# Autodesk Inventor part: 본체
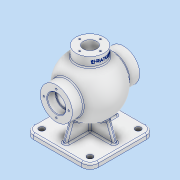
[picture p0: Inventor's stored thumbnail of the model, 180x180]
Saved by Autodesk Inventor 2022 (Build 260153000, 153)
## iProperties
Created: 2024-04
Part Number: 본체
Material: 알루미늄 6061
Document SubType Name: Modeling
Designer: Admin
Mass: 1526.9 g
Surface Area: 1171.86 cm^2
Volume: 565.52 cm^3
Density: 2.7 g/cm^3
Appearance: 알루미늄 - 평지
Author: Admin
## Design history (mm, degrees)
sketch "스케치1"
  geometry: C1 r 54 at (0, 0); 1 further point
  constraints: 1 centre point, 1 coincident
  dimensions: "d0" = 108 diameter of C1
extrude "돌출1" new body sketch "스케치1" stored distance "d1" = 108; taper "d2" = 0 deg
fillet "모깎기1" dims "d3" = 54
node "작업 평면2"
sketch "스케치2"
  geometry: L1 (-46.5, -62.5)-(46.5, -62.5); L2 (62.5, -46.5)-(62.5, 46.5); L3 (46.5, 62.5)-(-46.5, 62.5); L4 (-62.5, 46.5)-(-62.5, -46.5); L5 (-62.5, -62.5)-(62.5, 62.5); L6 (62.5, -62.5)-(-62.5, 62.5); A1 r 16 centre (46.5, 46.5) between (62.5, 46.5) and (46.5, 62.5); A2 r 16 centre (46.5, -46.5) between (46.5, -62.5) and (62.5, -46.5); A3 r 16 centre (-46.5, -46.5) between (-62.5, -46.5) and (-46.5, -62.5); A4 r 16 centre (-46.5, 46.5) between (-46.5, 62.5) and (-62.5, 46.5); 1 further point
  constraints: 12 end point, 8 point on circle, 8 point on line, 8 tangent, 4 centre point, 3 equal radius, 2 midpoint, 2 parallel, 1 horizontal, 1 perpendicular
  dimensions: "d6" = 125 distance of L6.start L5.end; "d7" = 125 distance of L5.start L6.start (= d6); "d8" = 16 radius of A1
extrude "돌출2" join sketch "스케치2" distance "d9" = 10; taper "d10" = 0 deg
sketch "스케치3"
  geometry: L1 (-112.8, 0)-(81.8, 0) reference; L2 (0, -87.5)-(0, 87.5) reference; L3 (-85, 87.5)-(-85, -87.5) reference; L4 (-85, 46.5)-(-85, 62.5) reference; L5 (0, 23.202)-(0, -23.202); L6 (-85, -62.5)-(-85, -46.5) reference; L7 (-85, 62.5)-(-75, 62.5) reference; L8 (-75, 46.5)-(-75, 62.5) reference; L9 (-75, -62.5)-(-75, -46.5) reference; L10 (-85, -46.5)-(-85, 46.5) reference; L11 (0, 23.202)-(-75, 50.5); L12 (-75, 50.5)-(-75, -50.5); L13 (-75, -50.5)-(0, -23.202); L14 (-75, -46.5)-(-75, 46.5) reference; 5 further points
  constraints: 8 end point, 3 midpoint, 2 symmetric about line, 1 parallel, 1 point on line, 1 vertical
  dimensions: "d13" = 20 deg angle of L7 L11; "d14" = 12 distance from line of L7 L11.end
extrude "돌출3" join sketch "스케치3" stored distance "d15" = 8; taper "d16" = 0 deg
sketch "스케치4"
  geometry: L1 (46.5, -75)-(-46.5, -75) reference; L2 (0, -112.8)-(0, 81.8) reference; L3 (-87.5, 0)-(87.5, 0) reference; L4 (-23.202, 0)-(23.202, 0); L5 (23.202, 0)-(50.5, -75); L6 (50.5, -75)-(-50.5, -75); L7 (-50.5, -75)-(-23.202, 0); L8 (-62.5, -85)-(-62.5, -75) reference; 3 further points
  constraints: 8 end point, 4 midpoint, 2 symmetric about line, 1 horizontal
  dimensions: "d17" = 20 deg angle of L8 L7; "d18" = 12 distance from line of L8 L6.end
extrude "돌출4" join sketch "스케치4" stored distance "d19" = 8; taper "d20" = 0 deg
node "작업 평면3"
sketch "스케치5"
  geometry: C1 r 31 at (0, 0); 1 further point
  constraints: 1 centre point, 1 coincident
  dimensions: "d22" = 62 diameter of C1
extrude "돌출5" join sketch "스케치5" distance "d23" = 130; taper "d24" = 0 deg
node "작업 평면4"
sketch "스케치6"
  geometry: C1 r 27 at (0, 0); 1 further point
  constraints: 1 centre point, 1 coincident
  dimensions: "d26" = 54 diameter of C1
extrude "돌출6" join sketch "스케치6" stored distance "d27" = 130; taper "d28" = 0 deg
sketch "스케치9"
  geometry: C1 r 15 at (0, 0); 1 further point
  constraints: 1 centre point, 1 coincident
  dimensions: "d29" = 30 diameter of C1
extrude "돌출7" cut sketch "스케치9" stored distance "d31" = 10; taper "d32" = 0 deg
sketch "스케치11"
  geometry: C1 r 13 at (0, 0); 1 further point
  constraints: 1 centre point, 1 coincident
  dimensions: "d33" = 26 diameter of C1
extrude "돌출8" cut sketch "스케치11" stored distance "d34" = 10; taper "d35" = 0 deg
sketch "스케치12"
  geometry: L1 (0, -91)-(0, 91) reference; L2 (0, -128.405)-(0, 139.748); A1 r 44 centre (0, 0) between (0, -44) and (0, 44); 3 further points
  constraints: 5 point on line, 2 end point, 2 point on circle, 1 centre point, 1 coincident
  dimensions: "d36" = 44 radius of A1
revolve "회전1" sketch "스케치12" stored, may be unused: angle "d37" = 90 deg
sketch "스케치13"
  geometry: C1 r 17.5 at (0, 0); 1 further point
  constraints: 1 centre point, 1 coincident
  dimensions: "d38" = 35 diameter of C1
extrude "돌출9" cut sketch "스케치13" distance "d39" = 16; taper "d40" = 0 deg
sketch "스케치14"
  geometry: L1 (87.5, 0)-(-87.5, 0) reference; L2 (0, -115)-(0, 95) reference; 2 further points
  constraints: 1 point on line
  dimensions: "d41" = 24 distance from line of L1 point (0, 24)
hole "구멍1" sketch "스케치14" at (0, 24) diameter "d42" = 3.242; stored, may be unused: countersink angle "d46" = 90 deg, drill point angle "d48" = 118 deg; dims "d43" = 12, "d44" = 4, "d45" = 2, "d47" = 15
sketch "스케치15"
  geometry: L1 (0, 91)-(0, -91) reference; 2 further points
  constraints: 1 point on line
  dimensions: "d52" = 20 distance of point (0, 0) point (0, -20)
hole "구멍2" sketch "스케치15" at (0, -20) diameter "d53" = 3.242; stored, may be unused: countersink angle "d57" = 90 deg, drill point angle "d59" = 118 deg; dims "d54" = 9, "d55" = 4, "d56" = 2, "d58" = 11
fillet "모깎기2" dims "d63" = 3
fillet "모깎기3" dims "d64" = 3
sketch "스케치16"
  geometry: A1 r 16 centre (-46.5, -46.5) between (-62.5, -46.5) and (-46.5, -62.5) reference; A2 r 16 centre (-46.5, 46.5) between (-46.5, 62.5) and (-62.5, 46.5) reference; A3 r 16 centre (46.5, 46.5) between (62.5, 46.5) and (46.5, 62.5) reference; A4 r 16 centre (46.5, -46.5) between (46.5, -62.5) and (62.5, -46.5) reference; 5 further points
  constraints: 4 coincident
hole "구멍3" sketch "스케치16" at (-46.5, -46.5), (-46.5, 46.5), (46.5, 46.5), (46.5, -46.5) diameter "d68" = 11; stored, may be unused: countersink angle "d72" = 90 deg, drill point angle "d74" = 118 deg; dims "d69" = 9, "d70" = 4, "d71" = 2, "d73" = 11
fillet "모깎기4" dims "d75" = 3
node "작업 평면5"
sketch "스케치17"
  geometry: L1 (-115, 0)-(95, 0) reference; L2 (65, -27)-(65, 27) reference; 2 further points
  constraints: 1 point on line, 1 other
  dimensions: "d77" = 9 distance from line of L2 point (56, 0)
feature "엠보싱1" sketch "스케치17" dims "d6" = 125, "d7" = 125 (= d6), "d8" = 16, "d78" = 0.5, "d79" = 0
chamfer "모따기2" distance "d80" = 1; stored, may be unused: second distance "d81" = 2, angle "d82" = 45 deg
fillet "모깎기5" dims "d83" = 0.6
node "솔리드1"
mirror "미러1"
pattern_circular "원형 패턴1" dims angle "d50" = 360 deg
mirror "미러2"
pattern_circular "원형 패턴2" dims angle "d61" = 360 deg
feature "A9D066F2-1C7D-4E18-AEED-F7BC21143FA4" dims "d68" = 11, "d69" = 9, "d70" = 4, "d71" = 2, "d72" = 90 deg, "d73" = 11, "d74" = 118 deg
other parameters: "d5" = -85, "d21" = 65, "d25" = 65, "d76" = 182.5
